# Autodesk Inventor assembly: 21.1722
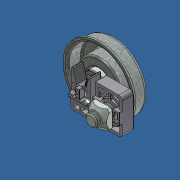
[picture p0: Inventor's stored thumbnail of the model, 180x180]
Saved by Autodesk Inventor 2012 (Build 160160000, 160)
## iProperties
Created: 2007-07
Part Number: 21.1722
Document SubType Name: Assembly
Designer: Andy Moles
Description: BEARING ASSEMBLY S
Vendor: S
Mass: 117.155 g
Surface Area: 177.198 cm^2
Volume: 23.6953 cm^3
Density: 4.94422 g/cm^3
Author: Andy Moles
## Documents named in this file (4)
- Y:\INVENTOR LIBRARIES\PARTS LIBRARY\BELT AND ROLLER CONVEYORS\21.1722 BEARING ASSEMBLY S.iam
- Y:\INVENTOR LIBRARIES\PARTS LIBRARY\BELT AND ROLLER CONVEYORS\SUBCOMPONENTS\21.1722 BEARING ASSEMBLY S HOUSING AND BALL BEARING.ipt
- Y:\INVENTOR LIBRARIES\PARTS LIBRARY\BELT AND ROLLER CONVEYORS\SUBCOMPONENTS\21.1721 BEARING ASSEMBLY S WASHER.ipt
- Y:\INVENTOR LIBRARIES\PARTS LIBRARY\BELT AND ROLLER CONVEYORS\22.1190 PULLEY CARRIER 36.iam
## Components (3 placed, 3 different names)
1. 21.1722 BEARING ASSEMBLY S HOUSING AND BALL BEARING:1 — Mate:3, Mate:4, Mate:7, Mate:8
2. 21.1721 BEARING ASSEMBLY S WASHER:1 — Mate:3, Mate:4
3. 22.1190 PULLEY CARRIER 36:1 [sub-assembly] — Mate:7, Mate:8, Angle:1
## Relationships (5: Mate 4, Angle 1)
- Mate:3: 21.1722 BEARING ASSEMBLY S HOUSING AND BALL BEARING:1 ↔ 21.1721 BEARING ASSEMBLY S WASHER:1
- Mate:4: 21.1722 BEARING ASSEMBLY S HOUSING AND BALL BEARING:1 ↔ 21.1721 BEARING ASSEMBLY S WASHER:1
- Mate:7: 21.1722 BEARING ASSEMBLY S HOUSING AND BALL BEARING:1 ↔ 22.1190 PULLEY CARRIER 36:1
- Mate:8: 21.1722 BEARING ASSEMBLY S HOUSING AND BALL BEARING:1 ↔ 22.1190 PULLEY CARRIER 36:1
- Angle:1: 22.1190 PULLEY CARRIER 36:1
